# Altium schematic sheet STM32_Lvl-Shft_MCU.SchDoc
size A; SheetNumber: 3; SheetTotal: 5
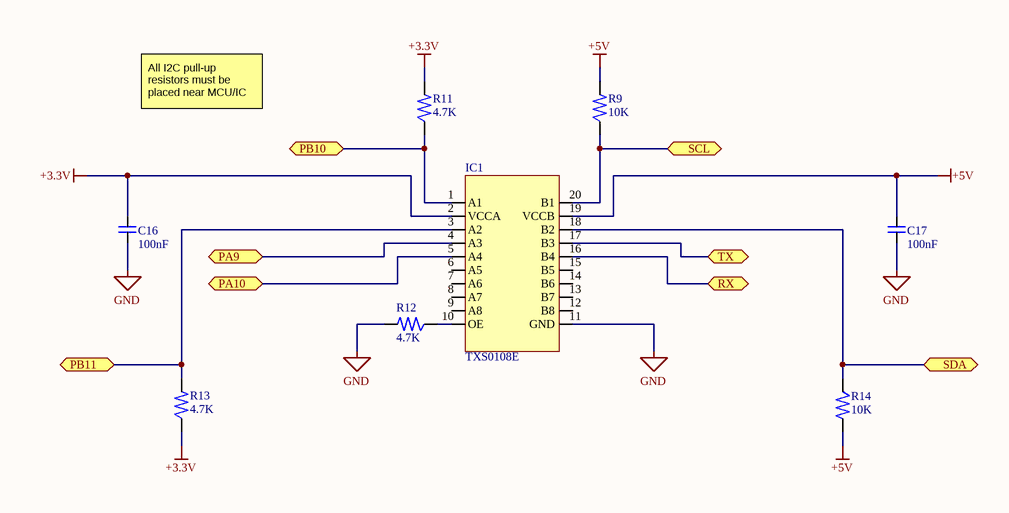
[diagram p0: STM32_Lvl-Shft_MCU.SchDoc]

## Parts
C16  100nF  [SMT_CAP_MODEL_1206(3216)_SAMSUNG]
C17  100nF  [SMT_CAP_MODEL_1206(3216)_SAMSUNG]
IC1  TXS0108E  [SMT_TXS0108E_IC]
R9  10K  [SMT_RES_MODEL_1206(3216)_ROHM]
R11  4.7K  [SMT_RES_MODEL_1206(3216)_ROHM]
R12  4.7K  [SMT_RES_MODEL_1206(3216)_ROHM]
R13  4.7K  [SMT_RES_MODEL_1206(3216)_ROHM]
R14  10K  [SMT_RES_MODEL_1206(3216)_ROHM]

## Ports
PA9 (bidir), PA10 (bidir), PB10 (bidir), PB11 (bidir), RX (bidir), SCL (bidir), SDA (bidir), TX (bidir)

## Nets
+3.3V: C16.1 IC1.2(VCCA) R11.1 R13.2
+5V: C17.1 IC1.19(VCCB) R9.1 R14.1
GND: C16.2 C17.2 IC1.11(GND) R12.1
PA9: IC1.4(A3) ; port PA9
PA10: IC1.5(A4) ; port PA10
PB10: IC1.1(A1) R11.2 ; port PB10
PB11: IC1.3(A2) R13.1 ; port PB11
RX: IC1.16(B4) ; port RX
SCL: IC1.20(B1) R9.2 ; port SCL
SDA: IC1.18(B2) R14.2 ; port SDA
TX: IC1.17(B3) ; port TX
NetIC1_10: IC1.10(OE) R12.2

Not connected (* = marked no-connect by the designer): IC1 6(A5) 7(A6) 8(A7) 9(A8) 12(B8) 13(B7) 14(B6) 15(B5)

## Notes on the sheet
- All I2C pull-up resistors must be placed near MCU/IC

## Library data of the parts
C16 C17 = SMT_CAP_MODEL_1206(3216)_SAMSUNG: SMT Samsung Ceramic Capacitor MODEL *V *nF 1206(3216)  CL31B104KBCNNNC(etc.)
IC1 = SMT_TXS0108E_IC: TXS0108E 8-BIT Bi-Directional Level Shifter 1.2-3.6V(A) 1.65-5.5V(B)
R9 R11-R14 = SMT_RES_MODEL_1206(3216)_ROHM: SMT ROHM Resistor MODEL 1206(3216) 1/4W MCR18ERTJ000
